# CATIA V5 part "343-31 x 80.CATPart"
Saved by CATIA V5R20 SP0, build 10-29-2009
Part number: 343-31 x 80
Definition: NONE
Nomenclature: 343-31 x 80
Source: Unknown
Description: 343-31 x 80
Bounding box of the stored display mesh (mm): x 0 to 80, y -22.5 to 22.5, z -22.5 to 22.5
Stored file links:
  C:\Users\Utente\Desktop\IO LAVORO\3D X SITO CF\X SITO\343-348\343-31 x 80.CATPart
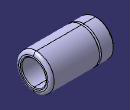
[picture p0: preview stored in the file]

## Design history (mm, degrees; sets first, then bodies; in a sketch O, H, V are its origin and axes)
Body1 "343-31 x 80" (main body)
  Solid1: solid without history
